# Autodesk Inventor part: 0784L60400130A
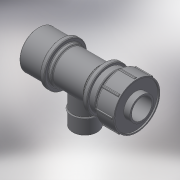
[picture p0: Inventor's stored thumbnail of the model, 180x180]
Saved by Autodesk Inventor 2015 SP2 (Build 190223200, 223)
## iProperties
Created: 2018-02
Part Number: 0784L60400130A
Material: Generic
Description: PLASSON MODULAR MALE TEE 40-1.1/4"-40
Document SubType Name: Modeling
Designer: KIM
Density: 1 g/cm^3
Appearance: Default
Author: KIM
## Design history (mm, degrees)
derived "0784L6.ipt"
feature "Solid1::0784L6.ipt"
feature "Solid2::0784L6.ipt"
tag "TaggingFeature1"
body "Solid1"
other parameters: "d26" = 38.55665, "d51" = 2, "d52" = 4.1, "d54" = 0, "d55" = 2, "d56" = 1, "d58" = 360 deg, "d60" = 1, "d63" = 1, "d65" = 0, "d67" = 0, "d69" = 158, "d70" = 71, "d71" = 41.91, "d73" = 79.54, "d74" = 64, "d75" = 35, "d76" = 75.44, "d77" = 36, "d79" = 37.2, "d80" = 34, "d82" = 7, "d83" = 73.8, "d84" = 73.8, "d86" = 61.5, "d88" = 65.6, "d89" = 57.4, "d90" = 9, "d91" = 34.2, "d92" = 69.7, "d93" = 39.6, "d94" = 32.4, "d95" = 7.2, "d96" = 48.6, "d97" = 47.4, "d98" = 57.4, "d99" = 41, "d100" = 36.9, "d101" = 22, "d102" = 31.4325, "d103" = 46.101, "d104" = 24.2, "E_" = 82, "H_" = 158, "l_1" = 36, "l_2" = 22, "A_" = 71, "d_" = 1, "R_" = 41.91, "ODP_" = 64, "LPT_" = 35
